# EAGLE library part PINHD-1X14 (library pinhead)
PIN HEADER
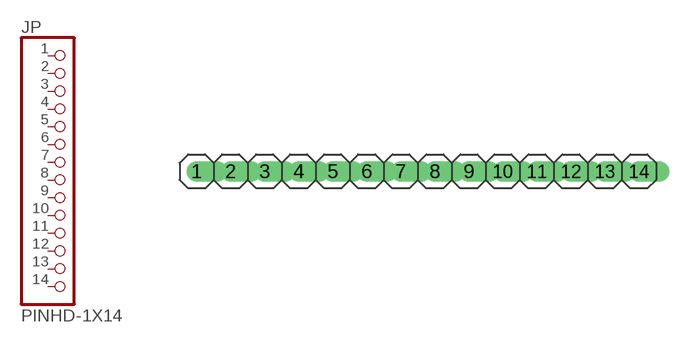
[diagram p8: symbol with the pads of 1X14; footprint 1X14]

Designator prefix JP

## PINHD-1X14  [1X14]
1  1  pas
2  2  pas
3  3  pas
4  4  pas
5  5  pas
6  6  pas
7  7  pas
8  8  pas
9  9  pas
10  10  pas
11  11  pas
12  12  pas
13  13  pas
14  14  pas

## Footprint 1X14 (pad centres in mm)
PIN HEADER
drill 1.016 offset: 1 -16.51,0; 2 -13.97,0; 3 -11.43,0; 4 -8.89,0; 5 -6.35,0; 6 -3.81,0; 7 -1.27,0; 8 1.27,0; 9 3.81,0; 10 6.35,0; 11 8.89,0; 12 11.43,0; 13 13.97,0; 14 16.51,0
